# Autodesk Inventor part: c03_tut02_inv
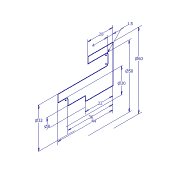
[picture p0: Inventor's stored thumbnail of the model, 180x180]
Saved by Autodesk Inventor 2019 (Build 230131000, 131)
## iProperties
Created: 2017-04
Part Number: c03_tut02_inv
Material: Generic
Document SubType Name: Modeling
Designer: CADCIM 00
Density: 1 g/cm^3
Appearance: Default
Author: CADCIM 00
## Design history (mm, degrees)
sketch "Sketch1"
  geometry: L1 (0, 0)-(-22, 0); L2 (-22, 0)-(-22, 4); L3 (-22, 4)-(-36, 4); L4 (-36, 4)-(-36, 8.5); L5 (-37.5, 10)-(-44, 10); L6 (-44, 10)-(-44, 16); L7 (-44, 16)-(-5.5, 16); L8 (-4, 17.5)-(-4, 23.5); L9 (-5.5, 25)-(-20, 25); L10 (-20, 25)-(-20, 30); L11 (-20, 30)-(0, 30); L12 (0, 30)-(0, 0); A1 r 1.5 centre (-5.5, 23.5) between (-4, 23.5) and (-5.5, 25); A2 r 1.5 centre (-37.5, 8.5) between (-36, 8.5) and (-37.5, 10); A3 r 1.5 centre (-5.5, 17.5) between (-5.5, 16) and (-4, 17.5)
  constraints: 24 end point, 11 perpendicular, 6 point on circle, 6 tangent, 3 centre point, 2 equal radius, 1 horizontal
  dimensions: "d0" = 8 diameter of L3 L1; "d1" = 20 diameter of L5 L1; "d2" = 32 diameter of L7 L1; "d3" = 50 diameter of L9 L1; "d4" = 60 diameter of L11 L1; "d5" = 4 distance between parallel lines of L8 L12; "d6" = 20 distance of L10.end L11.end; "d7" = 22 distance of L1.start L1.end; "d9" = 36 distance between parallel lines of L4 L12; "d10" = 44 distance between parallel lines of L12 L6; "d11" = 1.5 radius of A1
